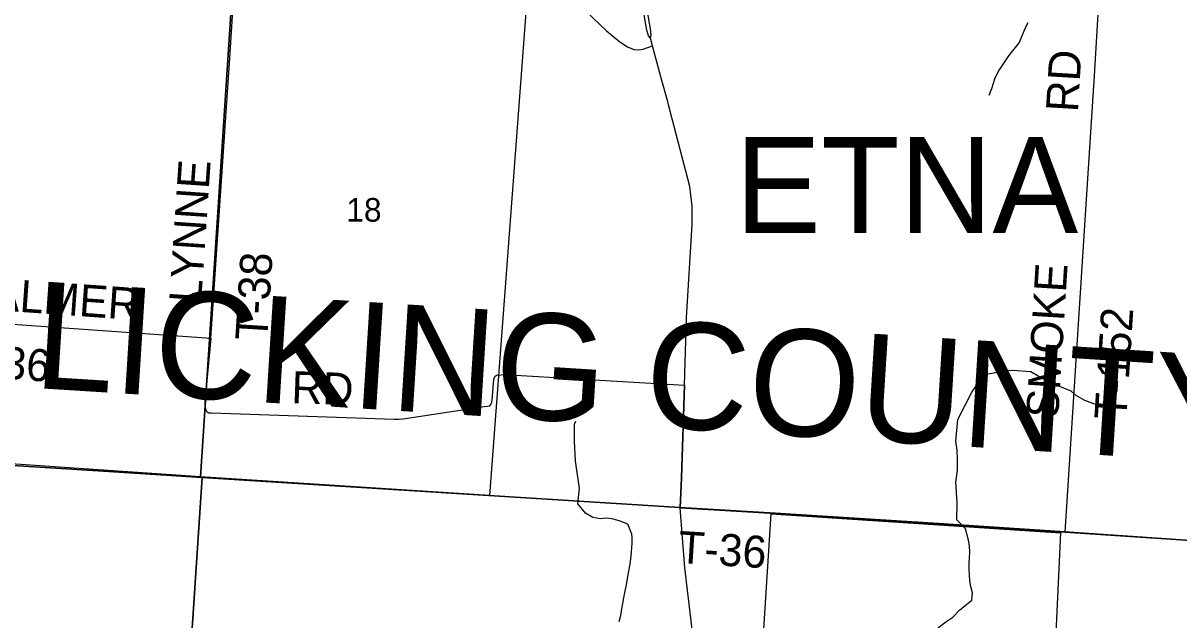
# Model space of a CAD drawing. Extents: x 0 to 34, y 0 to 22.
# Drawn here: x 4.778 to 6.826, y 15.479 to 16.537 of the extents above; entities that cross this region are included whole.
import ezdxf

# ---------------------------------------------------------------- set-up
doc = ezdxf.new("R2010")
doc.units = 0
for name, color, linetype in [('GM_X_Corporation', 7, 'Continuous'), ('GM_X_County_Text', 7, 'Continuous'), ('GM_X_Minor_River', 7, 'Continuous'), ('GM_X_Section', 7, 'Continuous'), ('GM_X_Section_Text', 7, 'Continuous'), ('GM_X_State_Route', 7, 'Continuous'), ('GM_X_Township_Road', 7, 'Continuous'), ('GM_X_Township_Road_Text', 7, 'Continuous'), ('GM_X_Township_Text', 7, 'Continuous'), ('SH_Cut_Line', 7, 'Continuous')]:
    doc.layers.add(name, color=color, linetype=linetype)

msp = doc.modelspace()

# ---------------------------------------------------------------- linework, layer by layer
at = {"layer": 'GM_X_Corporation'}
for points in [[(2.1, 15.9442), (2.1, 14.1), (4.9875, 14.1), (5.0611, 15.2147), (5.0952, 15.7318), (4.92, 15.7429), (4.5905, 15.7634), (4.2803, 15.787), (3.9945, 15.8088), (3.3132, 15.8609), (2.8362, 15.8952), (2.7799, 15.8989), (2.6921, 15.9056), (2.5827, 15.9132), (2.2903, 15.9292)], [(4.9875, 14.1), (8.9, 14.1), (8.9, 15.4827), (8.6741, 15.4976), (7.6503, 15.5653), (6.838, 15.6206), (6.624, 15.6351), (6.4, 15.6498), (6.1109, 15.6683), (5.9419, 15.6782), (5.0952, 15.7318), (5.0611, 15.2147)]]:
    msp.add_lwpolyline(points, close=True, dxfattribs=at)
msp.add_lwpolyline([(3.3132, 15.8609), (3.9945, 15.8088), (4.2803, 15.787), (4.5905, 15.7634), (4.92, 15.7429), (5.0952, 15.7318), (5.9419, 15.6782), (6.1109, 15.6683), (6.4, 15.6498), (6.624, 15.6351), (6.838, 15.6206)], dxfattribs=at)
at = {"layer": 'GM_X_Minor_River'}
for points in [[(6.5584, 16.5382), (6.5542, 16.5302), (6.5428, 16.5033), (6.5242, 16.4794), (6.5078, 16.4544), (6.5002, 16.44), (6.4941, 16.421), (6.4892, 16.4093)], [(6.448, 15.6404), (6.4327, 15.6565), (6.4332, 15.6865), (6.4306, 15.7234), (6.4337, 15.7446), (6.4337, 15.7636), (6.4334, 15.7799), (6.4307, 15.7959), (6.4346, 15.8342), (6.4586, 15.8816), (6.4688, 15.8964), (6.4874, 15.9153), (6.5185, 15.921), (6.531, 15.9217), (6.5639, 15.9197), (6.5794, 15.9098), (6.5893, 15.9049), (6.6025, 15.898), (6.6347, 15.885), (6.6426, 15.8782), (6.6589, 15.8686), (6.6937, 15.8556), (6.7126, 15.8476)], [(5.7609, 15.6849), (5.7637, 15.7123), (5.757, 15.7609), (5.7548, 15.7951), (5.7552, 15.8262), (5.7575, 15.8312)], [(5.8568, 15.631), (5.8495, 15.6487), (5.8359, 15.6541), (5.8215, 15.6581), (5.8113, 15.6593), (5.8007, 15.6583), (5.7875, 15.6607), (5.7747, 15.6681), (5.7609, 15.6849)], [(5.8343, 15.4761), (5.8371, 15.4867), (5.8391, 15.4985), (5.8407, 15.5079), (5.8424, 15.5182), (5.844, 15.5277), (5.8472, 15.5413), (5.8488, 15.5523), (5.8508, 15.5625), (5.8536, 15.5777), (5.8557, 15.5928), (5.8566, 15.6065), (5.8571, 15.616), (5.8572, 15.6255), (5.8568, 15.631)], [(6.3752, 15.3987), (6.3749, 15.409), (6.3774, 15.4253), (6.3798, 15.4355), (6.3833, 15.4457), (6.3902, 15.4563), (6.4009, 15.466), (6.4132, 15.4758), (6.4254, 15.484), (6.4372, 15.496), (6.4472, 15.5043), (6.4594, 15.514), (6.4603, 15.5269), (6.4574, 15.5379), (6.4556, 15.5482), (6.455, 15.5592), (6.4547, 15.5687), (6.4544, 15.579), (6.4549, 15.5892), (6.4554, 15.5987), (6.4548, 15.6101), (6.4534, 15.6204), (6.448, 15.6404)]]:
    msp.add_lwpolyline(points, dxfattribs=at)
at = {"layer": 'GM_X_Section'}
for points in [[(4.6741, 16.7675), (5.1577, 16.7346), (5.0919, 15.7328), (4.5921, 15.7668)], [(5.1577, 16.7346), (5.6796, 16.6989), (5.6042, 15.6994), (5.0919, 15.7328)], [(6.1034, 15.6668), (6.6161, 15.6333), (6.5689, 14.6183), (6.0392, 14.6526)]]:
    msp.add_lwpolyline(points, close=True, dxfattribs=at)
at = {"layer": 'GM_X_State_Route'}
for p, q in [((5.8935, 16.497), (5.8899, 16.5105)), ((5.9202, 16.3982), (5.9196, 16.4002))]:
    msp.add_line(p, q, dxfattribs=at)
for points in [[(5.8899, 16.5105), (5.8864, 16.515), (5.8831, 16.5248), (5.8795, 16.5448), (5.8776, 16.5569), (5.8754, 16.5789)], [(5.8899, 16.5105), (5.8906, 16.5166), (5.8897, 16.5275), (5.8861, 16.5475), (5.8824, 16.5718), (5.8809, 16.5812)], [(5.9196, 16.4002), (5.9096, 16.4359), (5.8935, 16.497)], [(5.9497, 15.895), (5.9537, 16.0147), (5.9636, 16.1804), (5.9636, 16.2126), (5.9593, 16.2474), (5.9218, 16.3925), (5.9202, 16.3982)], [(5.9421, 15.6777), (5.9448, 15.7309), (5.9497, 15.895)], [(5.9797, 15.1639), (5.9768, 15.3312), (5.9727, 15.3868), (5.9649, 15.4526), (5.9506, 15.5715), (5.9421, 15.6777)]]:
    msp.add_lwpolyline(points, dxfattribs=at)
at = {"layer": 'GM_X_Township_Road'}
for points in [[(5.1107, 15.9789), (5.1444, 16.4755), (5.1567, 16.672)], [(5.1567, 16.672), (5.3341, 16.6553), (5.6597, 16.6381), (5.7163, 16.6266), (5.7354, 16.6205), (5.7461, 16.6148), (5.7517, 16.6083), (5.7574, 16.6007), (5.7604, 16.5964), (5.7768, 16.5599), (5.7828, 16.5516), (5.7881, 16.5461), (5.8118, 16.524), (5.8355, 16.5045), (5.8491, 16.4956), (5.8559, 16.4925), (5.8608, 16.4909), (5.8689, 16.4902), (5.8764, 16.4915), (5.8935, 16.497)], [(6.6753, 16.4262), (6.6759, 16.4341), (6.6851, 16.5838)], [(6.6243, 15.6345), (6.6382, 15.8469), (6.6575, 16.1515), (6.6753, 16.4262)], [(4.6081, 16.0142), (5.1107, 15.9789), (5.0999, 15.8655), (5.0999, 15.8571), (5.1011, 15.8533), (5.1022, 15.8499), (5.1042, 15.848), (5.1072, 15.8465), (5.1114, 15.8465), (5.4356, 15.835), (5.4436, 15.8347), (5.4515, 15.8355), (5.5946, 15.8574), (5.6006, 15.8578), (5.6048, 15.8589), (5.6067, 15.8608), (5.6086, 15.865), (5.6089, 15.8684), (5.6122, 15.9057), (5.6133, 15.9091), (5.6144, 15.9114), (5.6163, 15.9126), (5.6178, 15.9137), (5.6213, 15.9133), (5.6287, 15.9145), (5.6507, 15.9132), (5.9497, 15.895)], [(5.9497, 15.895), (5.9448, 15.7309), (5.9421, 15.6777)], [(5.9421, 15.6777), (6.1111, 15.6678), (6.4002, 15.6492), (6.6243, 15.6345)], [(6.6243, 15.6345), (6.8382, 15.6201), (7.6505, 15.5648)]]:
    msp.add_lwpolyline(points, dxfattribs=at)
at = {"layer": 'SH_Cut_Line'}
for points in [[(8.9, 15.4827), (8.9, 20.9), (2.1, 20.9), (2.1, 15.9442), (2.2903, 15.9292), (2.5827, 15.9132), (2.6921, 15.9056), (2.7799, 15.8989), (2.8362, 15.8952), (3.3132, 15.8609), (3.9945, 15.8088), (4.2803, 15.787), (4.5905, 15.7634), (4.92, 15.7429), (5.0952, 15.7318), (5.9419, 15.6782), (6.1109, 15.6683), (6.4, 15.6498), (6.624, 15.6351), (6.838, 15.6206), (7.6503, 15.5653), (8.6741, 15.4976)], [(2.1, 15.9442), (2.1, 14.1), (8.9, 14.1), (8.9, 15.4827), (8.6741, 15.4976), (7.6503, 15.5653), (6.838, 15.6206), (6.624, 15.6351), (6.4, 15.6498), (6.1109, 15.6683), (5.9419, 15.6782), (5.0952, 15.7318), (4.92, 15.7429), (4.5905, 15.7634), (4.2803, 15.787), (3.9945, 15.8088), (3.3132, 15.8609), (2.8362, 15.8952), (2.7799, 15.8989), (2.6921, 15.9056), (2.5827, 15.9132), (2.2903, 15.9292)]]:
    msp.add_lwpolyline(points, close=True, dxfattribs=at)

# ---------------------------------------------------------------- texts
at = {"layer": 'GM_X_County_Text'}
msp.add_text('LICKING COUNTY', height=0.189394, rotation=356.3996, dxfattribs=at).set_placement((4.7947, 15.8905))
at = {"layer": 'GM_X_Section_Text'}
msp.add_text('18', height=0.04186, rotation=0, dxfattribs=at).set_placement((5.3507, 16.1853))
at = {"layer": 'GM_X_Township_Road_Text'}
for s, rotation, p in [('RD', 86.5461, (6.6471, 16.3787)), ('LYNNE', 86.1316, (5.0932, 16.04)), ('T-38', 86.4464, (5.2104, 15.9733)), ('SMOKE', 86.4609, (6.6121, 15.8357)), ('PALMER', 355.9261, (4.6693, 16.0326)), ('T-152', 86.3536, (6.7329, 15.8331)), ('T-36', 355.737, (4.6679, 15.9127)), ('RD', 358.0262, (5.2527, 15.8635)), ('T-36', 356.4465, (5.9375, 15.5801))]:
    msp.add_text(s, height=0.05682, rotation=rotation, dxfattribs=at).set_placement(p)
at = {"layer": 'GM_X_Township_Text'}
msp.add_text('ETNA', height=0.17045, rotation=0, dxfattribs=at).set_placement((6.0398, 16.1651))

doc.saveas('drawing.dxf')
